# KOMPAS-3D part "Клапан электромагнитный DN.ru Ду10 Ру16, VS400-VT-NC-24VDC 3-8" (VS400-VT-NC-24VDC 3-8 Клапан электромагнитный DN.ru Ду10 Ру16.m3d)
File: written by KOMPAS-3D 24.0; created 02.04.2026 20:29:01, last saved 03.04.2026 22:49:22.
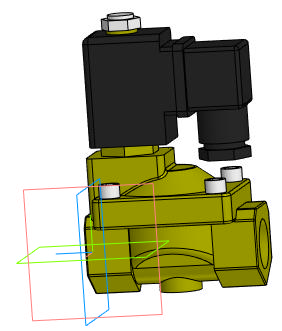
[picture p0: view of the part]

Document properties: Автор: artio; Полное имя файла: C:\Users\artio\OneDrive\Рабочий стол\Клапан электромагнитный DN.ru\VS400-VT-NC\VS400-VT-NC-24VDC 3-8 Клапан электромагнитный DN.ru Ду10 Ру16.m3d

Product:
- Body: Тело 1  | qty 1
    Масса: 1.030062
- Part/product: Клапан электромагнитный DN.ru Ду10 Ру16  | designation VS400-VT-NC-24VDC 3-8
    Масса: 0.797
    Раздел спецификации: Прочие изделия
    Примечание: D130-04732
    additional columns: ef56311e-7521-43dc-8291-0e6108b3d81d; VS400-ET-NC-220VAC 3-8; artio; c; Шероховатость не задана; Да

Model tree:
1. Операция без истории:1

Expressions: VS400-VT-NC-24VDC 3-8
